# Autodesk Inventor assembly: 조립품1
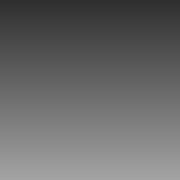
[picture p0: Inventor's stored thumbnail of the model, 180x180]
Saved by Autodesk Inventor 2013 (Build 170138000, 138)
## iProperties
Created: 2016-11
Part Number: 조립품1
Document SubType Name: Assembly
Designer: Administrator
Author: Administrator
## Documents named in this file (1)
- C:\Users\Administrator\Desktop\461107V1009\조립품1.iam
